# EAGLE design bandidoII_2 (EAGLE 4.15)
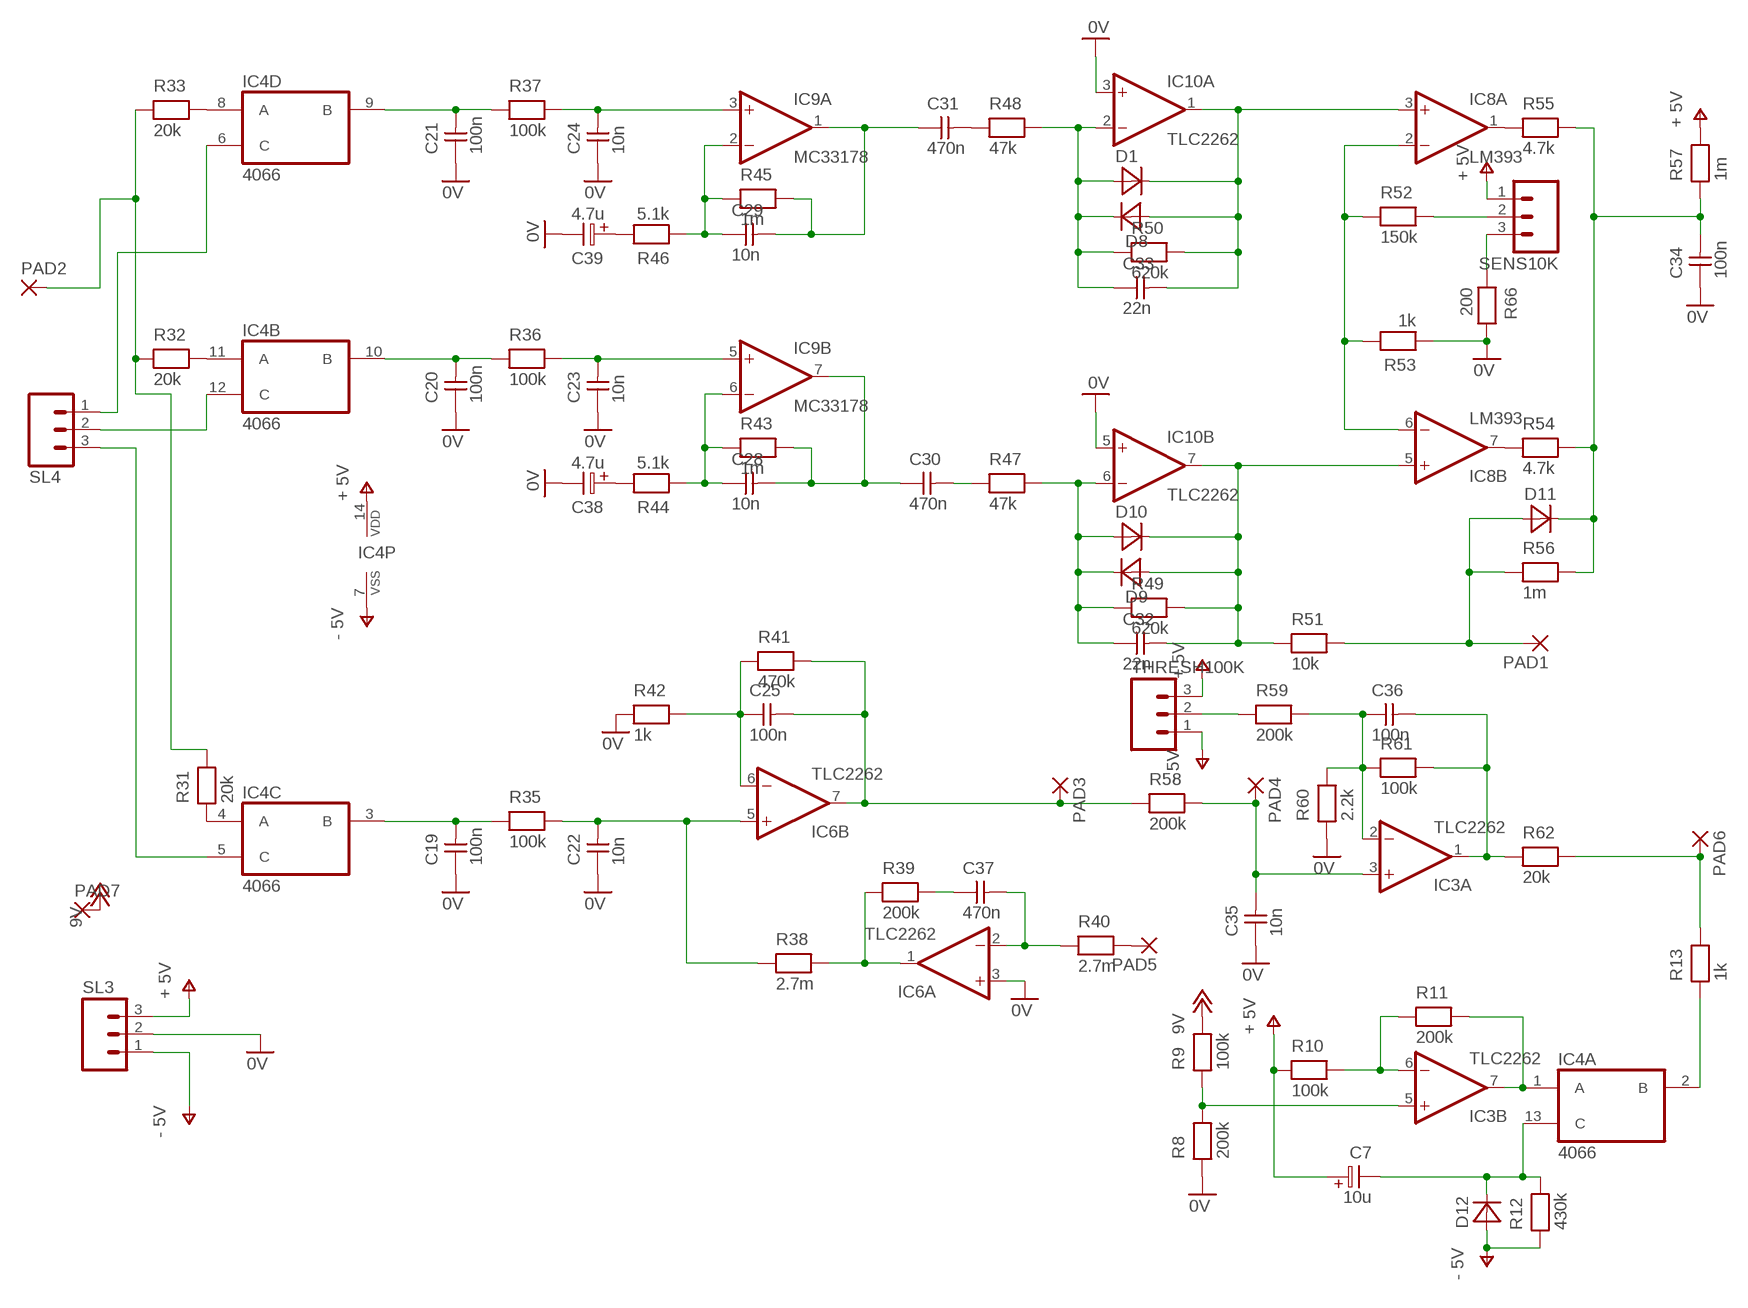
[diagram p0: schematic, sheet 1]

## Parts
C7  10u  ELC-2,5  [ES-2,5]
C19  100n  CAPNP-5  [C-5]
C20  100n  CAPNP-5  [C-5]
C21  100n  CAPNP-5  [C-5]
C22  10n  CAPNP-5  [C-5]
C23  10n  CAPNP-5  [C-5]
C24  10n  CAPNP-5  [C-5]
C25  100n  CAPNP-5  [C-5]
C28  10n  CAPNP-5  [C-5]
C29  10n  CAPNP-5  [C-5]
C30  470n  CAPNP-5  [C-5]
C31  470n  CAPNP-5  [C-5]
C32  22n  CAPNP-5  [C-5]
C33  22n  CAPNP-5  [C-5]
C34  100n  CAPNP-5  [C-5]
C35  10n  CAPNP-5  [C-5]
C36  100n  CAPNP-5  [C-5]
C37  470n  CAPNP-5  [C-5]
C38  4.7u  ELC-2,5  [ES-2,5]
C39  4.7u  ELC-2,5  [ES-2,5]
D1  DIODE-7,5  [D-7,5]
D8  DIODE-7,5  [D-7,5]
D9  DIODE-7,5  [D-7,5]
D10  DIODE-7,5  [D-7,5]
D11  DIODE-7,5  [D-7,5]
D12  DIODE-7,5  [D-7,5]
IC3  TLC2262  TL062P  [DIL08]
IC4  4066  4016N  [DIL14]
IC6  TLC2262  TL062P  [DIL08]
IC8  LM393  LM393N  [DIL08]
IC9  MC33178  LM358N  [DIL08]
IC10  TLC2262  TL062P  [DIL08]
PAD1  2,15/1,0  [2,15/1,0]
PAD2  2,15/1,0  [2,15/1,0]
PAD3  2,15/1,0  [2,15/1,0]
PAD4  2,15/1,0  [2,15/1,0]
PAD5  2,15/1,0  [2,15/1,0]
PAD6  2,15/1,0  [2,15/1,0]
PAD7  2,15/1,0  [2,15/1,0]
R8  200k  RESEU-7,5  [R-7,5]
R9  100k  RESEU-7,5  [R-7,5]
R10  100k  RESEU-7,5  [R-7,5]
R11  200k  RESEU-7,5  [R-7,5]
R12  430k  RESEU-7,5  [R-7,5]
R13  1k  RESEU-7,5  [R-7,5]
R31  20k  RESEU-7,5  [R-7,5]
R32  20k  RESEU-7,5  [R-7,5]
R33  20k  RESEU-7,5  [R-7,5]
R35  100k  RESEU-7,5  [R-7,5]
R36  100k  RESEU-7,5  [R-7,5]
R37  100k  RESEU-7,5  [R-7,5]
R38  2.7m  RESEU-7,5  [R-7,5]
R39  200k  RESEU-7,5  [R-7,5]
R40  2.7m  RESEU-7,5  [R-7,5]
R41  470k  RESEU-7,5  [R-7,5]
R42  1k  RESEU-7,5  [R-7,5]
R43  1m  RESEU-7,5  [R-7,5]
R44  5.1k  RESEU-7,5  [R-7,5]
R45  1m  RESEU-7,5  [R-7,5]
R46  5.1k  RESEU-7,5  [R-7,5]
R47  47k  RESEU-7,5  [R-7,5]
R48  47k  RESEU-7,5  [R-7,5]
R49  620k  RESEU-7,5  [R-7,5]
R50  620k  RESEU-7,5  [R-7,5]
R51  10k  RESEU-7,5  [R-7,5]
R52  150k  RESEU-7,5  [R-7,5]
R53  1k  RESEU-7,5  [R-7,5]
R54  4.7k  RESEU-7,5  [R-7,5]
R55  4.7k  RESEU-7,5  [R-7,5]
R56  1m  RESEU-7,5  [R-7,5]
R57  1m  RESEU-7,5  [R-7,5]
R58  200k  RESEU-7,5  [R-7,5]
R59  200k  RESEU-7,5  [R-7,5]
R60  2.2k  RESEU-7,5  [R-7,5]
R61  100k  RESEU-7,5  [R-7,5]
R62  20k  RESEU-7,5  [R-7,5]
R66  200  RESEU-7,5  [R-7,5]
SENS10K  M03  [03P]
SL3  M03  [03P]
SL4  M03  [03P]
THRESH100K  M03  [03P]

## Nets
0V: C19.1 C20.1 C21.1 C22.1 C23.1 C24.1 C34.1 C35.1 C38.2 C39.2 IC6.3(A:+IN) IC10.3(A:+IN) IC10.5(B:+IN) R8.1 R42.1 R53.1 R60.1 R66.2 SL3.2
+12V: PAD7.1(P) R9.2 ; supply symbol labelled 9V
N$1: C39.1 R46.2
N$2: C38.1 R44.2
N$3: C29.1 IC9.2(A:-IN) R45.1 R46.1
N$4: C29.2 C31.1 IC9.1(A:OUT) R45.2
N$5: C28.1 IC9.6(B:-IN) R43.1 R44.1
N$6: C28.2 C30.1 IC9.7(B:OUT) R43.2
N$7: C31.2 R48.1
N$8: C19.2 IC4.3(C:B) R35.1
N$9: C22.2 IC6.5(B:+IN) R35.2 R38.1
N$10: C23.2 IC9.5(B:+IN) R36.2
N$11: C20.2 IC4.10(B:B) R36.1
N$12: C21.2 IC4.9(D:B) R37.1
N$13: C24.2 IC9.3(A:+IN) R37.2
N$14: C30.2 R47.1
N$15: C33.1 D1.1(A) D8.2(K) IC10.2(A:-IN) R48.2 R50.1
N$16: C32.1 D9.2(K) D10.1(A) IC10.6(B:-IN) R47.2 R49.1
N$17: C33.2 D1.2(K) D8.1(A) IC8.3(A:+IN) IC10.1(A:OUT) R50.2
N$18: C32.2 D9.1(A) D10.2(K) IC8.5(B:+IN) IC10.7(B:OUT) R49.2 R51.1
N$19: IC8.2(A:-IN) IC8.6(B:-IN) R52.1 R53.2
N$20: IC8.7(B:OUT) R54.1
N$21: IC8.1(A:OUT) R55.1
N$22: C36.1 IC3.2(A:-IN) R59.2 R60.2 R61.1
N$23: R59.1 THRESH100K.2
N$24: R52.2 SENS10K.2
N$25: R66.1 SENS10K.3
N$26: C34.2 D11.2(K) R54.2 R55.2 R56.2 R57.1
N$27: D11.1(A) PAD1.1(P) R51.2 R56.1
N$28: C25.1 IC6.6(B:-IN) R41.1 R42.2
N$29: C25.2 IC6.7(B:OUT) PAD3.1(P) R41.2 R58.1
N$30: IC6.1(A:OUT) R38.2 R39.1
N$31: C37.1 R39.2
N$32: C37.2 IC6.2(A:-IN) R40.1
N$33: C35.2 IC3.3(A:+IN) PAD4.1(P) R58.2
N$34: PAD5.1(P) R40.2
N$35: C36.2 IC3.1(A:OUT) R61.2 R62.1
N$36: IC3.6(B:-IN) R10.2 R11.1
N$37: IC3.7(B:OUT) IC4.1(A:A) R11.2
N$38: IC4.11(B:A) R32.2
N$39: C7.2 D12.2(K) IC4.13(A:C) R12.2
N$40: IC3.5(B:+IN) R8.2 R9.1
N$41: IC4.4(C:A) R31.1
N$42: IC4.2(A:B) R13.1
N$43: PAD6.1(P) R13.2 R62.2
N$44: IC4.8(D:A) R33.2
N$45: PAD2.1(P) R31.2 R32.1 R33.1
N$47: IC4.6(D:C) SL4.1
N$48: IC4.12(B:C) SL4.2
N$49: IC4.5(C:C) SL4.3
V+: C7.1 IC4.14(P:VDD) R10.1 R57.2 SENS10K.1 SL3.3 THRESH100K.3 ; supply symbol labelled + 5V
V-: D12.1(A) IC4.7(P:VSS) R12.1 SL3.1 THRESH100K.1 ; supply symbol labelled - 5V

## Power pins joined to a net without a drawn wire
V+: IC3.8(P:V+) IC6.8(P:V+) IC8.8(P:V+) IC9.8(P:V+) IC10.8(P:V+)
V-: IC3.4(P:V-) IC6.4(P:V-) IC8.4(P:V-) IC9.4(P:V-) IC10.4(P:V-)

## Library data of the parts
C7 C38 C39 = discrete:ELC-2,5
C19-C25 C28-C37 = discrete:CAPNP-5
D1 D8-D12 = discrete:DIODE-7,5
IC3 IC6 IC10 = linear:TL062: OP AMP
IC4 = 40xx:4016: Quad bilateral ANALOG SWITCH
IC8 = linear:LM393: COMPARATOR
IC9 = linear:LM358: OP AMP
PAD1-PAD7 = wirepad:2,15/1,0: THROUGH-HOLE PAD
R8-R13 R31-R33 R35-R62 R66 = discrete:RESEU-7,5
SENS10K SL3 SL4 THRESH100K = con-amp-quick:M03: AMP QUICK CONNECTOR

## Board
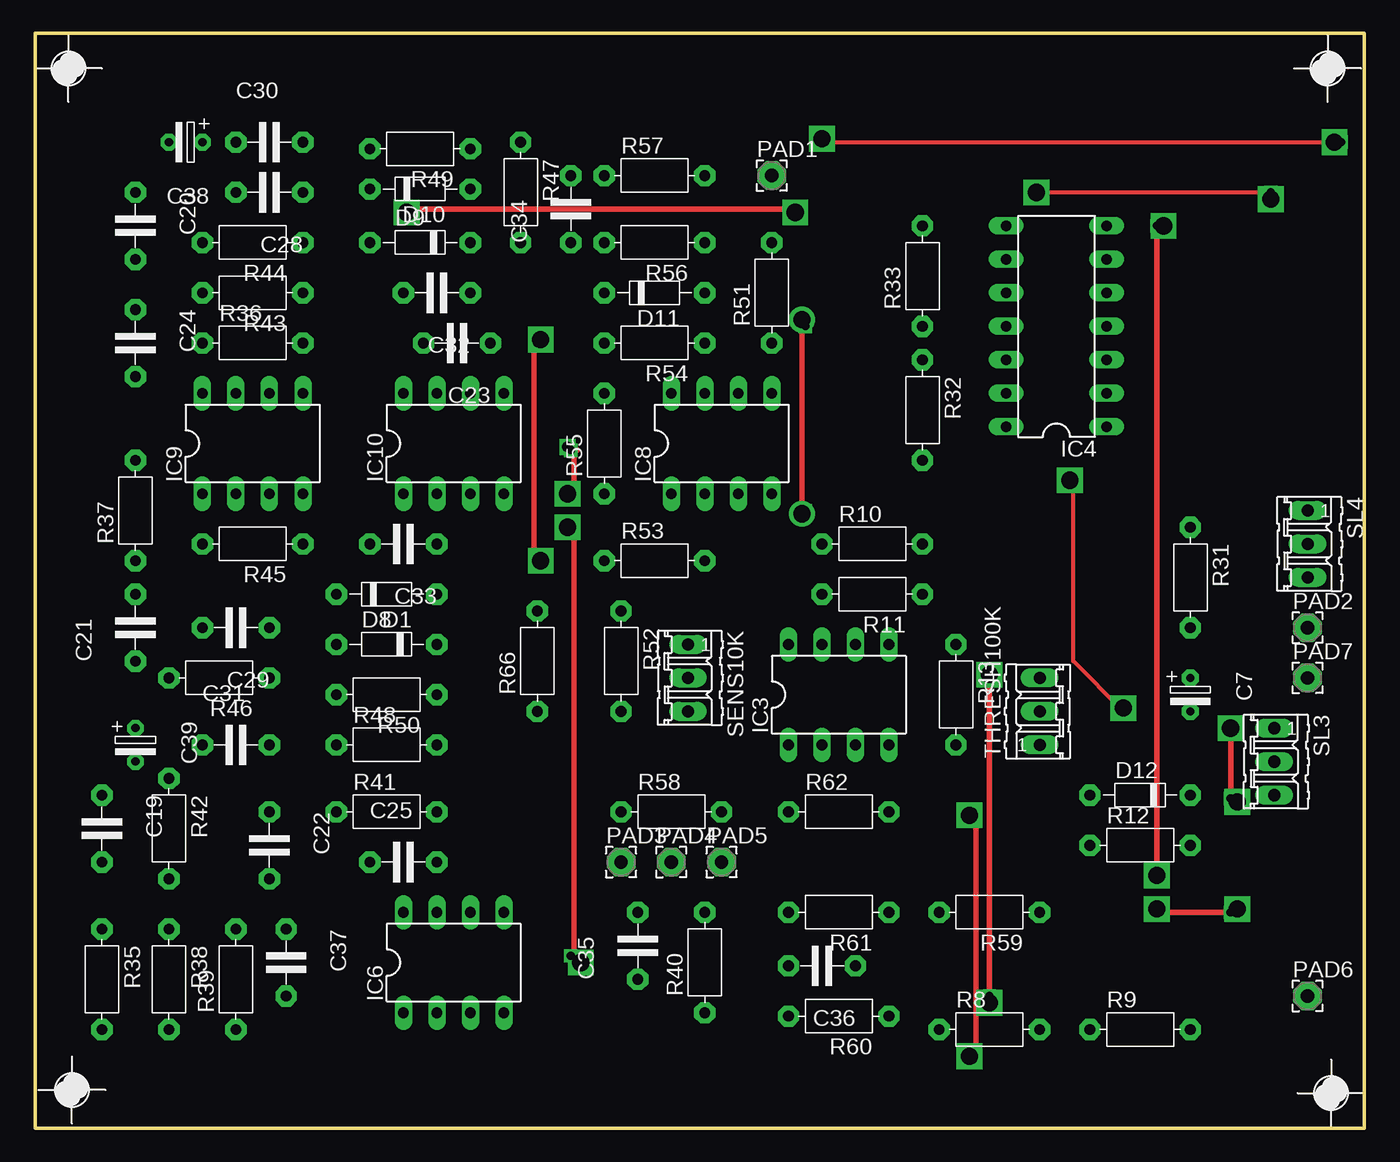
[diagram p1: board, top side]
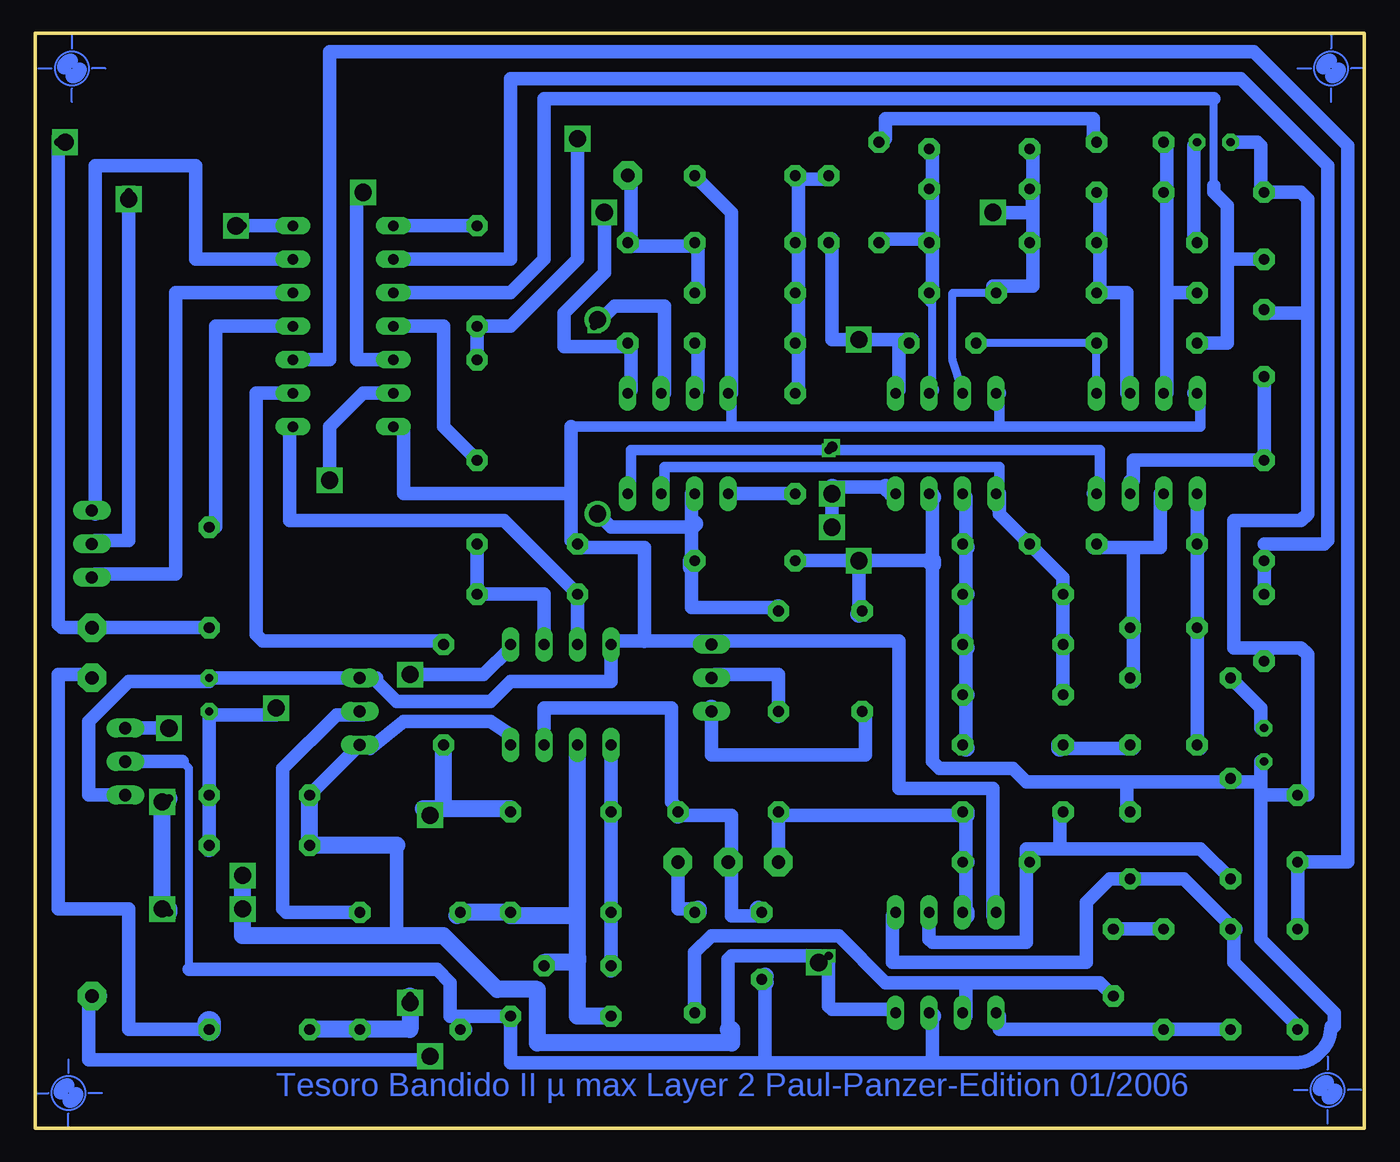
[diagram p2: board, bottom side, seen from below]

Size 100.76 x 83.05 mm. Coordinates in mm from the lower left corner, seen from the top.
Outline: 0,0 100.76,0 100.76,83.05 0,83.05 0,0
Copper layers (1*16): Top 0.035mm / dielectric 1.5mm / Bottom 0.035mm
Design rules "default": minimum track width 10mil, minimum drill 24mil, track to track 8mil, track to pad 8mil, pad to pad 8mil, via to via 8mil, smd to smd 8mil, copper to edge 40mil, drill to drill 8mil, minimum pad ring 10mil, minimum via ring 8mil, stop-mask expansion 4mil, vias tented up to drill 0mil, thermal gap 10mil

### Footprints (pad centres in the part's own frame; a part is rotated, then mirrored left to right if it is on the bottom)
ES-2,5 = drill 0.61 pad 1.27 octagon: 1 -1.27,0; 2 1.27,0
C-5 = drill 0.813 pad 1.6 octagon: 1 -2.54,0; 2 2.54,0
D-7,5 = drill 0.813 pad 1.6 octagon: 1 -3.81,0; 2 3.81,0
DIL08 = drill 0.813 long: 1 -3.81,-3.81; 2 -1.27,-3.81; 3 1.27,-3.81; 4 3.81,-3.81; 5 3.81,3.81; 6 1.27,3.81; 7 -1.27,3.81; 8 -3.81,3.81
DIL14 = drill 0.813 long: 1 -7.62,-3.81; 2 -5.08,-3.81; 3 -2.54,-3.81; 4 0,-3.81; 5 2.54,-3.81; 6 5.08,-3.81; 7 7.62,-3.81; 8 7.62,3.81; 9 5.08,3.81; 10 2.54,3.81; 11 0,3.81; 12 -2.54,3.81; 13 -5.08,3.81; 14 -7.62,3.81
2,15/1,0 = drill 1.016 pad 2.159 octagon: 1 0,0
R-7,5 = drill 0.813 pad 1.6 octagon: 1 -3.81,0; 2 3.81,0
03P = drill 0.914 long: 1 -2.54,0; 2 0,0; 3 2.54,0

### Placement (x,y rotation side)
C7  87.59,32.89 270 top
C19  5.04,22.73 270 top
C20  7.58,68.45 270 top
C21  7.58,37.97 90 top
C22  17.74,21.46 270 top
C23  31.97,59.56 180 top
C24  7.58,59.56 270 top
C25  27.9,20.19 0 top
C28  17.74,70.99 180 top
C29  15.2,37.97 180 top
C30  17.74,74.8 0 top
C31  15.2,29.08 0 top
C32  30.44,63.37 180 top
C33  27.9,44.32 180 top
C34  40.6,69.72 90 top
C35  45.68,13.84 90 top
C36  59.65,12.31 180 top
C37  19.01,12.57 270 top
C38  11.39,74.8 180 top
C39  7.58,29.08 270 top
D1  26.63,40.51 180 top
D8  26.63,36.7 0 top
D9  29.17,67.18 0 top
D10  29.17,71.24 180 top
D11  46.95,63.37 180 top
D12  83.78,25.27 0 top
IC3  60.92,32.89 0 top
IC4  77.43,60.83 90 top
IC6  31.71,12.57 0 top
IC8  52.03,51.94 0 top
IC9  16.47,51.94 0 top
IC10  31.71,51.94 0 top
PAD1  55.84,72.26 0 top
PAD2  96.48,37.97 0 top
PAD3  44.41,20.19 0 top
PAD4  48.22,20.19 0 top
PAD5  52.03,20.19 0 top
PAD6  96.48,10.03 0 top
PAD7  96.48,34.16 0 top
R8  72.35,7.49 0 top
R9  83.78,7.49 0 top
R10  63.46,44.32 0 top
R11  63.46,40.51 180 top
R12  83.78,21.46 0 top
R13  69.81,32.89 270 top
R31  87.59,41.78 270 top
R32  67.27,54.48 270 top
R33  67.27,64.64 90 top
R35  5.04,11.3 270 top
R36  16.47,59.56 0 top
R37  7.58,46.86 90 top
R38  10.12,11.3 270 top
R39  15.2,11.3 90 top
R40  50.76,12.57 90 top
R41  26.63,24 0 top
R42  10.12,22.73 270 top
R43  16.47,63.37 180 top
R44  16.47,67.18 180 top
R45  16.47,44.32 180 top
R46  13.93,34.16 180 top
R47  36.79,70.99 270 top
R48  26.63,29.08 0 top
R49  29.17,74.29 180 top
R50  26.63,32.89 180 top
R51  55.84,63.37 90 top
R52  44.41,35.43 270 top
R53  46.95,43.05 0 top
R54  46.95,59.56 180 top
R55  43.14,51.94 90 top
R56  46.95,67.18 180 top
R57  46.95,72.26 0 top
R58  48.22,24 0 top
R59  72.35,16.38 180 top
R60  60.92,8.5 180 top
R61  60.92,16.38 180 top
R62  60.92,24 0 top
R66  38.06,35.43 90 top
SENS10K  49.49,34.16 270 top
SL3  93.94,27.81 270 top
SL4  96.48,44.32 270 top
THRESH100K  76.16,31.62 90 top
U$1  [PASS-ROUND]  2.5,80.39 0 top
U$2  [PASS-ROUND]  98.01,80.39 0 top
U$3  [PASS-ROUND]  98.26,2.66 0 top
U$4  [PASS-ROUND]  2.76,2.92 0 top

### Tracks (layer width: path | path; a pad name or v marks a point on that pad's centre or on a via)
0V  (via drill 0.61, 1.3)
  Top 0.406: v38.06,43.05 37.81,43.05 37.81,59.56 v38.06,59.56
  Bottom 0.61: 89.62,27.81 89.12,27.3 89.12,12.06
  Bottom 1.016: 18,26.28 25.62,26.28 26.63,27.3 32.22,27.3 32.73,27.81 32.73,43.05 | C22.1 18,23.74 18,26.28 | 9.87,26.28 R42.1 | 9.87,26.28 18,26.28 | v38.32,43.05 v38.06,43.05 32.73,43.05 | v38.32,43.05 R53.1 | IC10.3 32.73,48.13 32.73,43.05 | R66.2 38.32,39.49 v38.32,43.05 | v38.32,43.05 38.32,38.98 | 32.73,43.05 v38.32,43.05 | C35.1 arc90 45.43,11.04 45.43,4.95 | 68.29,8.5 R60.1 64.73,4.95 45.43,4.95 | 68.29,8.5 68.29,7.49 | 68.29,8.5 69.3,8.5 69.3,11.04 70.32,12.06 89.12,12.06 | 89.62,27.81 SL3.2 | C38.2 8.09,74.8 7.84,74.54 7.84,70.99 C20.1 4.79,70.99 4.28,70.48 4.28,61.84 | C24.1 7.33,61.84 4.28,61.84 | 4.28,61.84 4.28,46.6 4.79,46.1 9.87,46.1 9.87,36.44 7.33,36.44 | C21.1 7.33,35.43 7.33,36.44 | 7.33,36.44 4.79,36.44 4.28,35.94 4.28,25.27 C19.1 7.84,25.27 | 7.84,26.28 9.87,26.28 | C39.2 7.84,27.81 7.84,27.05 | 7.84,27.05 7.84,26.28 | 7.84,25.27 7.84,26.28 | 7.84,14.35 7.84,25.27 | IC10.5 35.27,56 35.27,59.81 34.51,59.81 | 34.51,59.81 34.25,59.81 C23.1 34.51,59.81 | v38.06,59.56 v38.32,59.81 | v38.32,59.81 34.51,59.81 | v38.32,59.81 40.35,59.81 40.35,67.43 C34.1 | 32.73,4.95 32.73,8.5 | 32.73,4.95 45.43,4.95 | 32.73,4.95 5.3,4.95 arc-90 2.5,7.74 2.25,7.74 2.25,8.76 7.84,14.35 | 7.84,14.35 7.84,27.05
  Bottom 1.27: 45.43,11.04 C35.1 45.43,11.55 | 68.29,7.49 R8.1 | 32.73,8.5 IC6.3 | 37.81,43.05 v38.06,43.05 38.32,42.79 | 38.32,38.98 R66.2 | 32.73,43.05 32.98,43.05 32.73,42.79 | IC10.3 32.73,47.87
+12V
  Bottom 0.61: 96.23,34.41 96.23,34.16 PAD7.1
  Bottom 1.016: 96.23,34.41 99.02,34.41 99.02,16.63 93.69,16.63 93.69,7.49 R9.2
  Bottom 1.778: R9.2 87.59,8
N$1
  Bottom 1.016: R46.2 7.84,31.87 7.84,30.35 C39.1
N$2
  Bottom 1.016: R44.2 12.92,67.43 12.92,74.54 C38.1
N$3
  Bottom 1.016: 15.46,47.87 IC9.2 15.46,48.13 15.46,44.06 17.49,44.06 | 17.49,44.06 20.54,44.06 R45.1 20.03,44.06 | R46.1 17.49,33.9 17.49,37.97 C29.1 | C29.1 17.49,37.71 | C29.1 17.49,38.22 17.49,44.06
N$4
  Bottom 1.016: R45.2 IC9.1 | R45.2 12.41,44.06 | R45.2 12.66,38.22 12.41,37.97 C29.2 C31.1 12.41,28.82
N$5
  Bottom 1.016: C28.1 20.03,70.73 20.03,66.92 | 20.03,66.92 R44.1 | 20.03,66.92 20.03,63.37 R43.1 18,63.37 18,55.75 IC9.6
N$6
  Bottom 1.016: C30.1 14.95,74.54 14.95,70.99 C28.2 14.95,70.73 14.95,63.37 | IC9.7 14.95,55.75 14.95,63.37 | 14.95,63.37 R43.2
N$7
  Bottom 1.016: C31.2 17.49,28.82 22.82,28.82 23.08,29.08
  Bottom 1.27: R48.1 23.08,29.08 23.08,28.82
N$8
  Bottom 0.61: 79.97,58.29 IC4.3
  Bottom 1.016: 79.97,58.29 78.45,58.29 78.45,81.66 8.34,81.66 1.23,74.54 1.23,20.19 4.79,20.19 | 5.3,20.19 C19.2 4.79,20.19 | R35.1 4.79,15.11 5.04,15.36 5.04,19.93 4.79,20.19
N$9
  Bottom 1.016: R35.2 4.79,7.49 9.87,12.57 9.87,15.11 13.68,18.92 C22.2 19.27,18.92 21.04,17.14 21.04,12.57 35.78,12.57 35.78,16.12 IC6.5
  Bottom 1.27: 9.87,15.11 R38.1
N$10
  Bottom 0.61: C23.2 R36.2 IC9.5
N$11
  Bottom 0.61: 11.39,70.99 11.39,78.1
  Bottom 1.016: IC4.10 64.73,63.37 62.19,65.91 62.19,78.1 11.39,78.1 | R36.1 10.38,59.56 10.38,65.91 | 10.38,65.91 C20.2 | 10.38,65.91 10.38,69.97 11.39,70.99 11.39,71.5
N$12
  Bottom 0.61: 7.58,44.32 R37.1
  Bottom 1.016: R37.1 7.84,43.05 7.58,42.79 C21.2 | 7.58,44.32 3.01,44.32 2.76,44.57 2.76,73.02 9.36,79.62 64.73,79.62 64.73,65.91 IC4.9
N$13
  Bottom 0.61: IC9.3 17.74,49.14 17.74,49.4
  Bottom 1.016: C24.2 7.58,50.92 7.33,50.67 R37.2 17.49,50.67 17.49,49.14 17.74,49.14
N$14
  Bottom 1.016: C30.2 20.54,75.05 20.54,76.58 36.28,76.58 36.28,75.05 36.79,74.54 R47.1
N$15
  Bottom 1.016: IC10.2 30.19,47.87 30.19,44.06 30.19,40.51 30.19,36.44 30.19,32.89 | R50.1 30.19,32.63 30.19,28.82
  Bottom 1.27: 30.19,44.06 C33.1 | D1.1 30.19,40.51 30.44,40.76 | 30.19,36.44 D8.2 | R50.1 30.19,32.89 30.44,33.14 | R48.2 30.19,28.82
N$16
  Bottom 0.61: C32.1 32.98,62.61 | 32.73,56 32.73,63.37
  Bottom 1.016: 32.73,63.37 C32.1 32.73,63.62 32.73,67.43 | IC10.6 32.73,56 | 32.73,67.43 D9.2 33.24,67.43 36.79,67.43 R47.2 | 32.73,67.43 32.73,71.5 | R49.1 32.73,74.54 32.73,71.5 | 32.73,71.5 D10.1
N$17
  Bottom 0.61: IC10.1 27.9,46.86
  Bottom 0.813: IC8.3 53.05,48.13 53.05,50.16 27.65,50.16 27.65,48.13
  Bottom 1.016: R50.2 D8.1 | D8.1 22.57,36.95 | D8.1 22.82,40.25 22.57,40.51 D1.2 22.82,41.78 C33.2 27.65,46.6 27.65,48.13 IC10.1
N$18  (via drill 0.61, 1.3)
  Top 0.406: v27.9,69.72 v57.87,69.72
  Bottom 0.61: D10.2 25.36,69.72 | IC10.7 30.44,56 31.2,58.29 31.2,63.37 C32.2
  Bottom 1.016: 25.11,67.43 D9.1 | 25.11,67.43 25.11,63.88 28.16,63.88 28.16,63.37 C32.2 | 25.11,71.5 D10.2 | 25.11,67.43 25.11,69.46 | 25.11,69.46 25.11,71.5 | R49.2 25.11,74.54 25.11,71.5 | v27.9,69.72 27.65,69.46 25.11,69.46 | IC8.5 55.59,56 55.59,59.3 R51.1 56.1,59.3 60.67,59.3 60.67,61.84 57.62,64.89 v57.62,69.46 v57.87,69.72
N$19  (via drill 0.61, 1.3)
  Top 0.406: v58.38,60.83 58.13,60.83 58.13,46.86 | v58.13,46.6 58.13,46.86 | 58.13,46.86 v58.38,46.86
  Bottom 0.61: 51.02,45.59 50.76,45.59
  Bottom 1.016: 44.41,39.49 51.02,39.49 51.02,43.05 | R53.2 51.02,43.3 51.02,45.59 57.11,45.59 v58.13,46.6 v58.38,46.86 | IC8.2 51.02,48.13 51.02,46.1 50.76,45.84 | v58.38,60.83 56.86,62.35 53.05,62.35 53.05,55.75 IC8.6
  Bottom 1.27: 51.02,45.59 50.76,45.84 | 51.02,42.54 51.02,43.05 R53.2 51.02,42.79 | R52.1 44.41,39.49
N$20
  Bottom 1.016: R54.1 50.51,59.3 50.51,56 IC8.7
N$21
  Bottom 1.016: 42.89,48.13 R55.1 IC8.1
N$22
  Bottom 1.27: 64.73,16.12 64.99,16.38 R59.2 68.8,16.12 | 59.65,13.08 59.65,12.57 62.19,12.57 C36.1 | 59.65,13.08 59.65,16.12 | 59.65,16.12 IC3.2 | R60.2 59.65,8.5 59.65,13.08 | 64.73,16.12 R61.1 | 59.65,16.12 64.73,16.12
N$23
  Bottom 1.016: R59.1 81.75,16.38 82,16.63 82,27.3 77.94,31.36 75.91,31.36 THRESH100K.2
N$24
  Bottom 1.016: SENS10K.2 49.24,34.41 44.41,34.41 R52.2
  Bottom 1.27: R52.2 44.41,31.36
N$25
  Bottom 1.016: R66.1 37.81,31.36 37.81,28.32 49.49,28.32 SENS10K.3
  Bottom 1.27: SENS10K.3 49.49,31.87
N$26
  Bottom 1.016: C34.2 40.86,72 42.89,72 | 42.89,72 R57.1 | 42.89,66.92 42.89,72 | 42.89,66.92 R56.2 | 42.89,66.92 42.89,63.37 D11.2 42.89,63.11 42.89,59.81 R54.2 42.89,59.3 42.89,55.75 R55.2
N$27
  Bottom 1.016: PAD1.1 55.59,72 55.59,66.92 | 55.59,66.92 R51.2 | 50.51,66.92 55.59,66.92 | D11.1 50.51,63.37 50.51,66.92 | 50.51,66.92 R56.1
N$28
  Bottom 0.61: C25.1 25.11,20.19 25.11,20.7
  Bottom 1.016: R42.2 12.41,21.2 23.08,21.2 | 23.08,21.2 25.62,21.2 25.62,20.19 | R41.1 23.08,23.74 23.08,21.2 | IC6.6 32.98,14.35 32.73,14.09 25.62,14.09 25.62,20.19 | 25.62,20.19 C25.1
N$29
  Bottom 1.016: R41.2 30.7,23.74 44.41,23.74 PAD3.1 | 30.19,24 30.19,20.19 30.19,16.12 IC6.7
  Bottom 1.27: 44.41,23.74 R58.1 | 30.19,23.74 30.19,24 R41.2 | 30.19,16.12 30.19,16.38 IC6.7 | 30.19,20.19 C25.2
N$30
  Bottom 1.016: R39.1 15.46,7.49 | R38.2 R39.1 | R39.1 27.65,7.49 27.65,8.5 IC6.1
N$31
  Bottom 1.016: R39.2 C37.1
N$32
  Bottom 1.016: C37.2 20.03,11.04 30.19,11.04 | IC6.2 30.19,8.5 30.19,11.04 | 30.19,11.04 36.28,11.04 39.84,14.6 49.49,14.6 50.76,13.33 R40.1
N$33
  Bottom 0.61: 62.19,30.35 IC3.3
  Bottom 1.016: 52.03,23.74 47.97,23.74 47.97,20.19 47.97,16.12 45.43,16.12 C35.2 | 62.19,30.35 62.19,31.87 52.54,31.87 52.54,24.76 52.03,24.25 R58.2
  Bottom 1.27: 47.97,20.19 PAD4.1 48.48,20.19 | 45.94,16.63 45.94,16.38 C35.2 | 52.03,23.74 R58.2
N$34
  Bottom 1.016: PAD5.1 52.03,16.63 50.51,16.63 R40.2
  Bottom 1.27: 50.51,16.63 50.51,16.38 R40.2
N$35
  Bottom 1.016: IC3.1 R62.1 R61.2 C36.2
  Bottom 1.27: R62.1 57.11,23.74 | C36.2 57.11,12.06
N$36
  Bottom 1.016: R10.2 R11.1 62.19,40.51 IC3.6
N$37
  Bottom 1.016: IC3.7 R11.2 65.24,46.1 81.5,46.1 81.5,53.21 IC4.1
N$38
  Bottom 1.016: R32.2 69.81,53.21 69.81,60.83 IC4.11
N$39  (via drill 0.61, 1.3)
  Top 0.254: v82.51,31.62 v82.51,31.87
  Top 0.305: v78.7,49.4 78.7,35.43 v82.51,31.62
  Bottom 0.254: D12.2 87.59,25.52
  Bottom 1.016: 87.59,21.2 D12.2 | v82.51,31.62 82.51,31.36 87.59,31.36 | IC4.13 75.91,55.75 78.45,53.21 v78.45,49.14 v78.7,49.4 | 87.59,25.52 87.59,31.36 | C7.2 87.59,31.36
  Bottom 1.27: R12.2 87.59,21.2
N$40  (via drill 0.61, 1.3)
  Top 0.406: v72.35,9.52 v72.35,34.16
  Bottom 1.016: IC3.5 64.73,36.44 66.76,34.41 v72.35,34.41 v72.35,34.16
  Bottom 1.27: v72.35,10.03 v72.35,9.52 72.35,7.49 R8.2 | R8.2 76.42,7.49 | R8.2 R9.1
N$41
  Bottom 1.016: IC4.4 87.08,60.83 87.08,45.59 R31.1
N$42
  Bottom 1.016: IC4.2 84.04,55.75 84.04,37.46 83.53,36.95 69.81,36.95 R13.1
N$43  (via drill 0.61)
  Top 0.406: v71.08,5.2 71.34,4.95 71.34,24 v71.08,24
  Bottom 0.61: 96.74,10.03 PAD6.1
  Bottom 1.016: 96.74,10.03 96.74,5.2 v71.08,5.2
  Bottom 1.27: 69.81,24.25 R13.2 | v71.08,24 71.34,24.25 69.81,24.25 | R62.2 64.73,24.25 69.81,24.25
  Bottom 1.778: PAD6.1 96.23,10.03
N$44
  Bottom 1.016: R33.2 IC4.8
N$45  (via drill 0.61, 1.3)
  Top 0.254: v59.65,74.8 v59.65,75.05
  Top 0.305: v59.65,74.8 v99.02,74.8
  Bottom 1.016: 96.23,37.97 R31.2 | v99.02,74.8 99.02,38.22 98.77,37.97 96.23,37.97 | 96.23,37.97 PAD2.1 | R32.1 R33.1 64.73,60.83 59.65,65.91 v59.65,74.8
N$46  (via drill 1.3)
  other vias: 28.16,69.46
N$47
  Bottom 1.016: IC4.6 88.61,65.91 88.61,73.02 96.23,73.02 96.23,46.6 SL4.1
N$48  (via drill 0.61, 1.3)
  Top 0.254: v76.16,70.99 v75.91,70.99
  Top 0.305: v76.16,70.99 v93.69,70.99
  Bottom 1.016: v93.69,70.99 v93.69,70.48 93.69,44.57 96.23,44.57 SL4.2 | IC4.12 76.42,58.29 76.42,70.99 v76.16,70.99
N$49
  Bottom 1.016: IC4.5 90.13,63.37 90.13,42.03 96.23,42.03 SL4.3
N$50  (via drill 1.3)
  other vias: 98.51,74.8
N$51  (via drill 1.3)
  other vias: 85.56,68.45
N$52  (via drill 1.3)
  other vias: 41.36,12.57
N$53  (via drill 1.3)
  other vias: 70.83,5.46
N$54  (via drill 1.3)
  other vias: 70.83,23.74
N$55  (via drill 1.3)
  other vias: 58.13,61.34
N$56  (via drill 0.8)
  other vias: 40.35,51.68
V+
  Bottom 0.254: 87.34,34.16 C7.1
  Bottom 0.61: 54.57,36.95 54.57,36.7 | 74.89,34.16 THRESH100K.3
  Bottom 0.813: 60.16,53.21 47.97,53.21 | 47.97,53.21 47.97,55.75 | 47.97,53.21 27.65,53.21 | 27.65,53.21 27.65,55.75 | 27.65,53.21 12.41,53.21 12.41,55.75 IC9.8
  Bottom 1.016: 54.57,36.95 56.86,36.95 | 54.57,36.95 49.49,36.95 SENS10K.1 49.24,36.95 35.27,36.95 35.27,25.78 28.16,25.78 28.16,16.12 IC6.8 | 59.65,44.06 54.57,44.06 54.57,36.95 | 74.89,34.16 74.89,33.9 73.37,32.38 66.26,32.38 64.73,33.9 57.11,33.9 IC3.8 | THRESH100K.3 87.34,34.16 87.59,33.9 93.69,33.9 96.74,30.86 96.74,25.27 SL3.3 93.69,25.27 | R57.2 47.97,69.46 47.97,55.75 IC8.8 | IC9.8 12.92,55.75 | 27.65,55.75 IC10.8 | 60.16,48.13 60.16,44.57 59.65,44.57 59.65,44.06 | 60.16,48.13 60.16,53.21 | 59.65,44.06 R10.1 | IC4.14 72.86,53.21 72.86,48.13 60.16,48.13
  Bottom 1.27: 56.86,36.95 IC3.8
V-  (via drill 0.61, 1.3)
  Top 0.254: v40.35,48.13 v40.6,48.13
  Top 0.406: v40.6,48.13 40.86,48.13 40.86,51.43 | v40.6,13.08 40.86,13.08 40.86,45.59 v40.6,45.59 | v85.05,18.92 v85.05,19.17 v85.05,68.45 | v90.64,16.38 v85.05,16.38 85.05,16.12 | v90.64,25.01 v90.64,30.09 | 40.86,51.43 41.11,51.43 | 40.35,51.43 v40.6,51.43 40.86,51.43
  Bottom 0.61: THRESH100K.1 75.4,29.08 74.89,29.08
  Bottom 0.813: IC9.4 20.03,48.13 20.03,51.43 v40.6,51.43 55.59,51.43 55.59,48.13 IC8.4
  Bottom 1.016: 40.35,48.64 36.28,48.64 | v40.6,45.59 v40.35,45.59 v40.35,48.13 40.6,48.38 | 73.37,14.6 73.37,21.46 | v90.64,30.35 SL3.1 | D12.1 THRESH100K.1 | IC3.4 64.73,29.84 66.26,30.86 72.86,30.86 75.4,28.82 75.4,29.08 | 80.99,68.45 IC4.7 v85.05,68.45 | 48.22,7.49 48.22,12.82 47.97,13.08 v40.6,13.08 40.6,9.27 40.35,9.01 35.78,9.01 IC6.4 | IC9.4 20.54,48.13
  Bottom 1.27: v90.64,25.01 91.15,25.01 v91.15,24.76 v91.15,16.63 90.64,16.63 v90.64,16.38 | v90.64,30.09 v90.64,30.35 | D12.1 R12.1 73.37,21.46 | v85.05,16.38 85.05,16.12 | v85.05,16.38 v85.05,16.63 v85.05,18.92 | v85.05,16.38 85.05,14.6 73.37,14.6 69.81,14.6 65.75,10.54 62.7,10.54 62.7,6.47 47.97,6.47 47.97,7.49 48.22,7.49 | 40.6,48.38 40.35,48.64 | IC10.4 35.78,48.13 36.28,48.64

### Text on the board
Bottom: Tesoro Bandido II µ max Layer 2 Paul-Panzer-Edition 01/2006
